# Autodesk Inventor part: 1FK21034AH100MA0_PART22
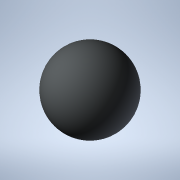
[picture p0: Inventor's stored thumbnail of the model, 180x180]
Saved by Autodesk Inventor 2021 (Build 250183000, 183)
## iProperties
Created: 2025-04
Part Number: 1FK21034AH100MA0_PART22
Material: Generic
Catalog Web Link: www.3dfindit.com
Description: -Servo synchronous motor
Document SubType Name: Modeling
Designer: psAdmin
Mass: 0.113097 g
Surface Area: 1.13097 cm^2
Volume: 0.113097 cm^3
Density: 1 g/cm^3
Appearance: PSOLRGB-212-217-219
Category: PARTsolutions
Title: 1FK21034AH100MA0_PART22
Author: Cadenas PARTsolutions
Comments: Servo synchronous motor
Sending System: PARTsolutions
Preprocessor: ST-DEVELOPER v19.3
PSOL_IDENT_0: {$CADENAS_DATA/23d-libs/siemens_ag/_cat_/39/97/1fk21034ah100ma0.prj},216 {VTYP=3D},{NB=1FK21034AH100
PSOL_IDENT_1: MA0_PART22},{LINA=1FK21034AH100MA0_PART22},{NN=1FK21034AH100MA0_PART22},{NOPRJ=TRUE},{DATE=19.08.202
PSOL_IDENT_2: 5 14:00:33},{GEOMDATE=30.07.2025 02:02:21},{VERSION=},{LINEID=10},{WBVAR=},{WBNUMERIC=}  {NB=1FK2103
PSOL_IDENT_3: 4AH100MA0_PART22},{LINA=1FK21034AH100MA0_PART22},{KT=DUMMY},{PREVIEW=../../../_pool_/d3/78/p_d211_xx
PSOL_IDENT_4: _00934j.png},{DESCSHORT=SIMOTICS S-1FK2 HD, SINAMICS S210 3AC 400V-480V, 1.01 Nm, 4500 rpm},{DESCLON
PSOL_IDENT_5: G=SIMOTICS S-1FK2 HD servo motor M0=1.27 Nm; PN = 0.48 kW at nN=4500 rpm (380-480 V); PN = 0.3 kW at
PSOL_IDENT_6: nN=2500 rpm (200-240 V); with holding brake; degree of protection IP64; cylindrical shaft D14 x 30
PSOL_IDENT_7: mm; absolute encoder 22-bit + 12-bit multiturn (encoder AM22DQC); with OCC interface; plug size M17,
PSOL_IDENT_8: rotatable; SIMOTICS S-1FK2 servomotorfor a wide range of uses in industrial environments. SIMOTICS
PSOL_IDENT_9: S‑1FK2 servomotors are compact synchronous motors with a high dynamic performance that set themselve
PSOL_IDENT_10: s apart as a result of their high power density, degree of protection and overload capability. The m
PSOL_IDENT_11: otors are available in two variants: as High Dynamic variant (highest dynamic performance as a resul
PSOL_IDENT_12: t of the low intrinsic moment of inertia for applications demanding a high dynamic performance with
PSOL_IDENT_13: low moved masses) - and as Compact variant (precise and stable closed-loop control for medium up to
PSOL_IDENT_14: large moved masses as a result of a medium intrinsic moment of inertia). SIMOTICSS‑1FK2 servomotors
PSOL_IDENT_15: fully exploit their strengths in a system with the SINAMICSS210 frequency converter and simple conne
PSOL_IDENT_16: ction using the one cable connection (OCC). Advantages include the short control and positioning tim
PSOL_IDENT_17: es, fast and precise correction of disturbing quantities as well as stable control with a high dynam
PSOL_IDENT_18: ic performance. The servo motors can be configured to address a wide range of requirements. For exam
PSOL_IDENT_19: ple with and without holding brake, IP64 or IP65 degree of protection, singleturn or multiturn absol
PSOL_IDENT_20: ute encoders - to name just a few. Further, the servomotors are available in different shaft heights
PSOL_IDENT_21: extending from 20 to 100. A shaft sealing ring is available to achieve an IP65 degree of protection
PSOL_IDENT_22: and for subsequent mounting at the motor or as spare part. SIMOTICS - the optimum motor for each an
PSOL_IDENT_23: d every motion control application.},{INTNO=195125454019},{SUPPLIERALTNO=1FK2103-4AH10-0MA0},{MANUID=
PSOL_IDENT_24: 1FK21034AH100MA0},{MANUNAME=Siemens},{MANUTYPEDESC=SYNCHRONOUS MOTOR 1FK2 HD 1,27 NM},{AAU732=SIMOTI
PSOL_IDENT_25: CS},{AAO057=S-1FK2},{AAU734=SIMOTICS S-1FK2 HD servo motor M0=1.27 Nm; PN = 0.48 kW at nN=4500 rpm (
PSOL_IDENT_26: 380-480 V); PN = 0.3 kW at nN=2500 rpm (200-240 V); with holding brake; degree of protection IP64; c
PSOL_IDENT_27: ylindrical shaft D14 x 30 mm; absolute encoder 22-bit + 12-bit multiturn (encoder AM22DQC); with OCC
PSOL_IDENT_28: interface; plug size M17, rotatable;},{AAW338=SYNCHRONOUS MOTOR 1FK2 HD 1,27 NM},{AAO742=SIMOTICS},
PSOL_IDENT_29: {AAO663=4034106444921},{NOCUPEROU=1},{PRICEQUANTITY=1},{QUANTITYMIN=1},{QUANTITYINT=1},{CTN=85015100
PSOL_IDENT_30: },{COO=RO},{AAO676=1FK2103-4AH10-0MA0},{AAO677=Siemens AG},{ORDERUNIT=C62},{CONTENTUNIT=C62}
NB: 1FK21034AH100MA0_PART22
NT: Servo synchronous motor
NBSYN: $MANUID._PART22
LINA: 1FK21034AH100MA0_PART22
CATALOG: SIEMENS
PREVIEW: ../../../_pool_/d3/78/p_d211_xx_00934j.png
DESCSHORT: SIMOTICS S-1FK2 HD, SINAMICS S210 3AC 400V-480V, 1.01 Nm, 4500 rpm
DESCLONG: SIMOTICS S-1FK2 HD servo motor M0=1.27 Nm; PN = 0.48 kW at nN=4500 rpm (380-480 V); PN = 0.3 kW at nN=2500 rpm (200-240 V); with holding brake; degree of protec
INTNO: 195125454019
SUPPLIERALTNO: 1FK2103-4AH10-0MA0
MANUID: 1FK21034AH100MA0
MANUNAME: Siemens
MANUTYPEDESC: SYNCHRONOUS MOTOR 1FK2 HD 1,27 NM
AAU732: SIMOTICS
AAO057: S-1FK2
AAU734: SIMOTICS S-1FK2 HD servo motor M0=1.27 Nm; PN = 0.48 kW at nN=4500 rpm (380-480 V); PN = 0.3 kW at nN=2500 rpm (200-240 V); with holding brake; degree of protec
AAW338: SYNCHRONOUS MOTOR 1FK2 HD 1,27 NM
AAO742: SIMOTICS
AAO663: 4034106444921.0
NOCUPEROU: 1
PRICEQUANTITY: 1
QUANTITYMIN: 1
QUANTITYINT: 1
CTN: 85015100
COO: RO
ARTICLENO: 1FK21034AH100MA0_PART22
BOMINFO: 1FK21034AH100MA0_PART22
CREATOR: CADENAS GmbH
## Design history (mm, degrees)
feature "2025_04_17_15_09_00_0361"
body "Solid1"
